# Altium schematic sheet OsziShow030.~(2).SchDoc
size A4
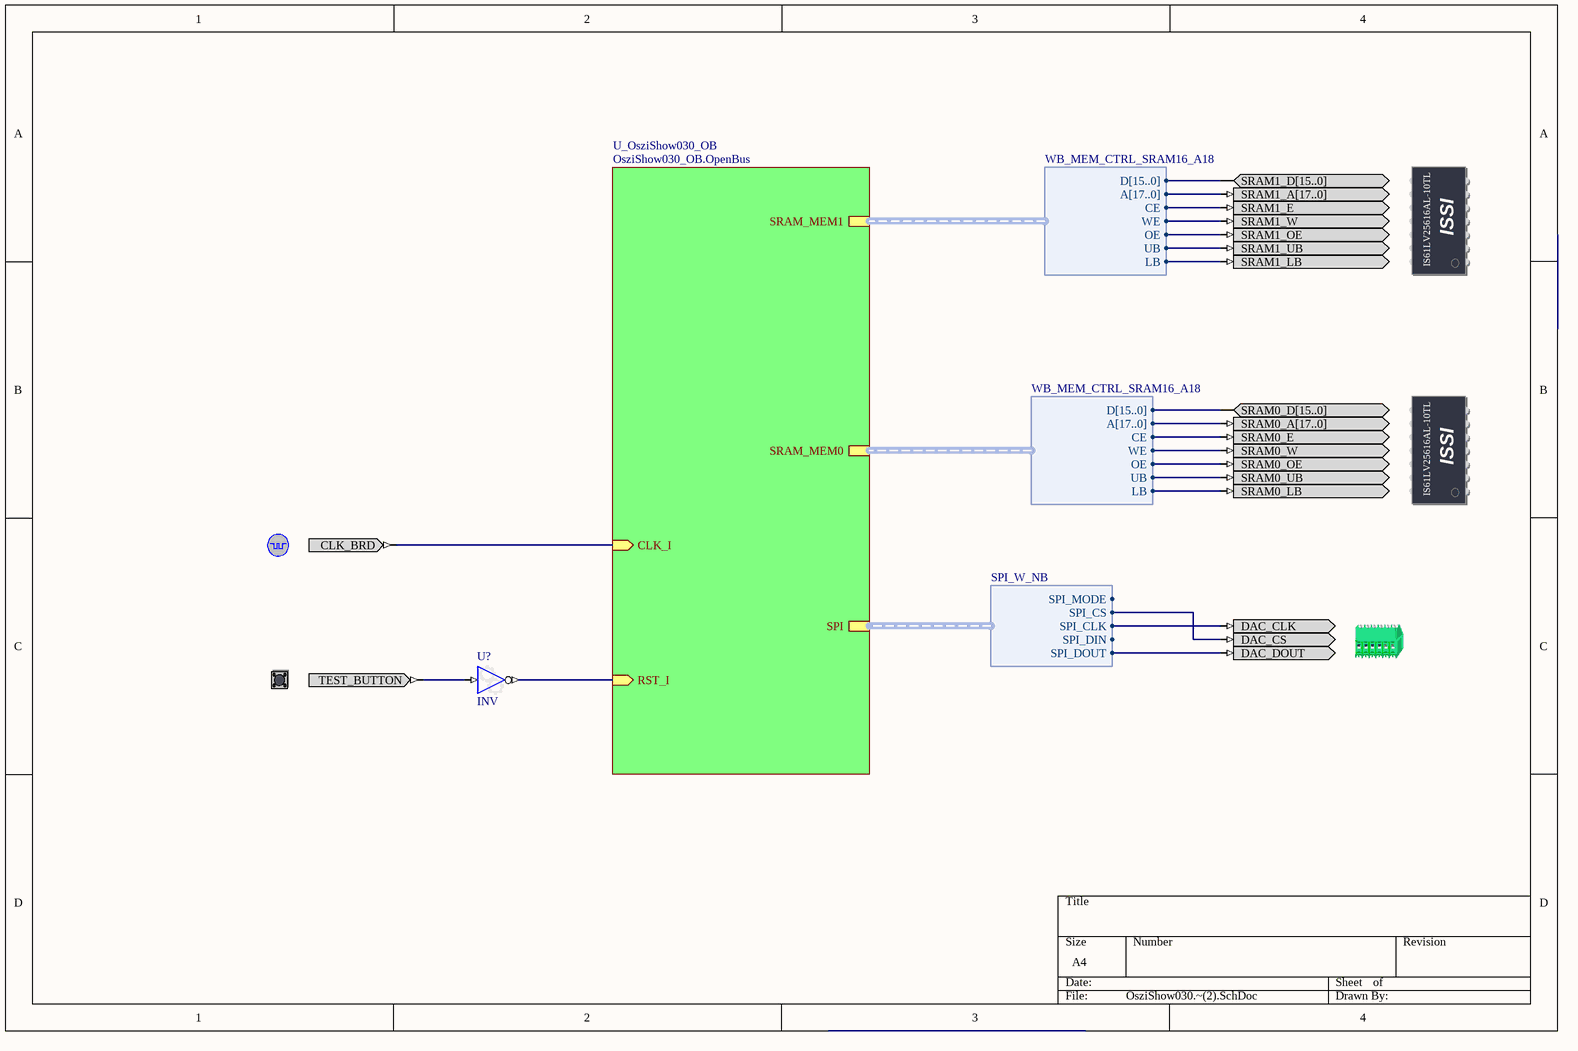
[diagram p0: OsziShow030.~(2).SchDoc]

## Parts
(Parts that share a designator on the sheet are numbered #1, #2 ... from top to bottom, then left to right.)
?#1  SRAM1  (value not drawn)
?#2  SRAM0  (value not drawn)
?#3  CLOCK_BOARD  (value not drawn)
?#4  ADCDAC  (value not drawn)
?#5  TEST_BUTTON  (value not drawn)
U?  INV

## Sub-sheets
U_OsziShow030_OB = OsziShow030_OB.OpenBus: SRAM_MEM0 (harness WB_MEM_CTRL_SRAM16_A18), SRAM_MEM1 (harness WB_MEM_CTRL_SRAM16_A18), SPI (harness SPI_W_NB), RST_I (in), CLK_I (in)

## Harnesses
WB_MEM_CTRL_SRAM16_A18: D[15..0], A[17..0], CE, WE, OE, UB, LB
SPI_W_NB: SPI_DOUT, SPI_DIN, SPI_CLK, SPI_CS, SPI_MODE

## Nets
Net?#1_SRAM1_E: ?#1.SRAM1_E ; sheet U_OsziShow030_OB/SRAM_MEM1.CE
Net?#1_SRAM1_LB: ?#1.SRAM1_LB ; sheet U_OsziShow030_OB/SRAM_MEM1.LB
Net?#1_SRAM1_OE: ?#1.SRAM1_OE ; sheet U_OsziShow030_OB/SRAM_MEM1.OE
Net?#1_SRAM1_UB: ?#1.SRAM1_UB ; sheet U_OsziShow030_OB/SRAM_MEM1.UB
Net?#1_SRAM1_W: ?#1.SRAM1_W ; sheet U_OsziShow030_OB/SRAM_MEM1.WE
Net?#2_SRAM0_E: ?#2.SRAM0_E ; sheet U_OsziShow030_OB/SRAM_MEM0.CE
Net?#2_SRAM0_LB: ?#2.SRAM0_LB ; sheet U_OsziShow030_OB/SRAM_MEM0.LB
Net?#2_SRAM0_OE: ?#2.SRAM0_OE ; sheet U_OsziShow030_OB/SRAM_MEM0.OE
Net?#2_SRAM0_UB: ?#2.SRAM0_UB ; sheet U_OsziShow030_OB/SRAM_MEM0.UB
Net?#2_SRAM0_W: ?#2.SRAM0_W ; sheet U_OsziShow030_OB/SRAM_MEM0.WE
Net?#3_CLK_BRD: ?#3.CLK_BRD ; sheet U_OsziShow030_OB/CLK_I
Net?#4_DAC_CLK: ?#4.DAC_CLK ; sheet U_OsziShow030_OB/SPI.SPI_CLK
Net?#4_DAC_CS: ?#4.DAC_CS ; sheet U_OsziShow030_OB/SPI.SPI_CS
Net?#4_DAC_DOUT: ?#4.DAC_DOUT ; sheet U_OsziShow030_OB/SPI.SPI_DOUT
Net?#5_TEST_BUTTON: ?#5.TEST_BUTTON U?.I
NetU?_O: U?.O ; sheet U_OsziShow030_OB/RST_I

Not connected (* = marked no-connect by the designer): ?#1 SRAM1_A[17..0] SRAM1_D[15..0]; ?#2 SRAM0_A[17..0] SRAM0_D[15..0]

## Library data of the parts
?#1 = SRAM1: Free Static RAM - Daughterboard; PortComponent: True
?#2 = SRAM0: Free Static RAM - Daughterboard; PortComponent: True
?#3 = CLOCK_BOARD: Global System Clock Supply; PortComponent: True
?#4 = DAC: Digital Analog Converter; PortComponent: True
?#5 = TEST_BUTTON: Test / Reset Button; PortComponent: True
U? = INV: Configurable Inverter; ConfigurationParameters: {}Version[1.1]{}SignalCount[1]{}SignalWidth0[1]{}OutputOption0[Inverted]{}EnableMode[None]{}ShowPinNames[False]{}; ConfiguratorName: GENERIC_BUFFER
